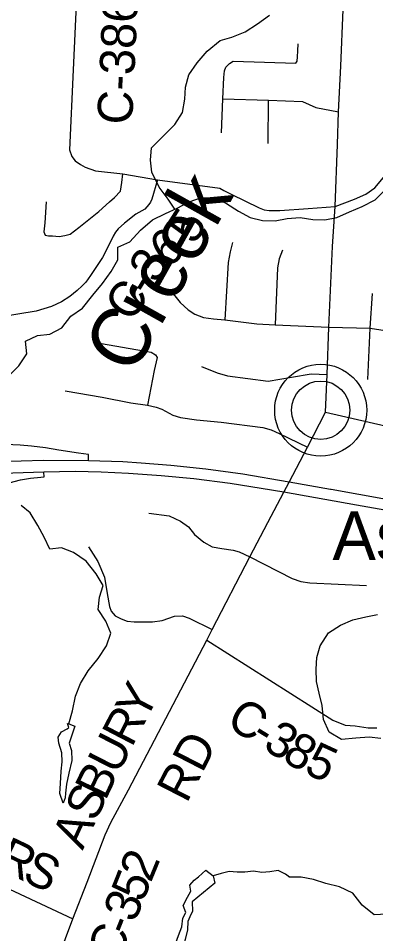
# Model space of a CAD drawing. Extents: x 0 to 34, y 0 to 22.
# Drawn here: x 4.659 to 4.948, y 14.941 to 15.682 of the extents above; entities that cross this region are included whole.
import ezdxf

# ---------------------------------------------------------------- set-up
doc = ezdxf.new("R2010")
doc.units = 0
for name, color, linetype in [('GM_X_County_Road', 7, 'Continuous'), ('GM_X_County_Road_Text', 7, 'Continuous'), ('GM_X_Interchange_Ramps', 7, 'Continuous'), ('GM_X_Interstate_Route', 7, 'Continuous'), ('GM_X_Minor_River', 7, 'Continuous'), ('GM_X_Minor_River_Text', 7, 'Continuous'), ('GM_X_Township_Road', 7, 'Continuous'), ('GM_X_Unincorporated', 7, 'Continuous'), ('GM_X_Unincorporated_Location', 7, 'Continuous'), ('GM_X_Unincorporated_Text', 7, 'Continuous')]:
    doc.layers.add(name, color=color, linetype=linetype)

msp = doc.modelspace()

# ---------------------------------------------------------------- linework, layer by layer
at = {"layer": 'GM_X_County_Road'}
msp.add_line((4.70658, 15.70999), (4.70334, 15.63991), dxfattribs=at)
for points in [[(4.9073, 15.36317), (4.90862, 15.39378), (4.91013, 15.43191), (4.91317, 15.4971), (4.91508, 15.52949), (4.91706, 15.57965), (4.91782, 15.606), (4.91971, 15.64287), (4.9218, 15.68884), (4.92284, 15.70486), (4.92616, 15.78353)], [(4.70334, 15.63991), (4.70036, 15.57533), (4.70231, 15.56995), (4.705, 15.56653), (4.70916, 15.56359), (4.71307, 15.56139), (4.72134, 15.55847), (4.74348, 15.55606), (4.77156, 15.55104)], [(4.77156, 15.55104), (4.82203, 15.54434), (4.82522, 15.54256), (4.83122, 15.53957), (4.8537, 15.52844), (4.8578, 15.52693), (4.86196, 15.52625), (4.87037, 15.52625), (4.89351, 15.52777), (4.91508, 15.52949), (4.9309, 15.53552), (4.93992, 15.53948), (4.94729, 15.54461), (4.95571, 15.55461), (4.97796, 15.58453), (4.98766, 15.58316)], [(4.77156, 15.55104), (4.76692, 15.53545), (4.76598, 15.53298), (4.76455, 15.53114), (4.76143, 15.52741), (4.75393, 15.52322), (4.74487, 15.51614), (4.73961, 15.51137), (4.73766, 15.5088), (4.7357, 15.5055), (4.73264, 15.49926), (4.72714, 15.48826), (4.71736, 15.47358), (4.71369, 15.46845), (4.71148, 15.46615)], [(4.71148, 15.46615), (4.71075, 15.46539), (4.70672, 15.46148), (4.70073, 15.45671), (4.694, 15.4523), (4.68593, 15.44864), (4.67345, 15.44497), (4.64191, 15.43982)], [(4.86082, 15.27396), (4.87359, 15.29836), (4.8779, 15.30659), (4.89275, 15.33488), (4.9073, 15.36317)], [(4.9073, 15.36317), (4.9557, 15.35212), (4.99857, 15.34333), (5.06724, 15.33122), (5.08926, 15.32733), (5.21435, 15.30577), (5.22323, 15.30424), (5.33237, 15.28586), (5.36275, 15.28074)], [(4.69129, 14.92158), (4.70295, 14.95352), (4.7147, 14.983), (4.72914, 15.02146), (4.73385, 15.03124), (4.74797, 15.05769), (4.81147, 15.17891), (4.81564, 15.1874), (4.8463, 15.24622), (4.86082, 15.27396)], [(4.31741, 15.19756), (4.3442, 15.17748), (4.34773, 15.17417), (4.35138, 15.1682), (4.35443, 15.16053), (4.37218, 15.09005), (4.37522, 15.08099), (4.3785, 15.0784), (4.38451, 15.07627), (4.3984, 15.07474), (4.42425, 15.07063), (4.44456, 15.06505), (4.46552, 15.0586), (4.52756, 15.03587), (4.55688, 15.0232), (4.58247, 15.0098), (4.70295, 14.95352)], [(4.81147, 15.17891), (4.91321, 15.11411), (4.92317, 15.11007), (4.9315, 15.1095), (4.9419, 15.10792), (4.94892, 15.10794)]]:
    msp.add_lwpolyline(points, dxfattribs=at)
at = {"layer": 'GM_X_Interchange_Ramps'}
for points in [[(4.71588, 15.32379), (4.71581, 15.32902), (4.70754, 15.33007), (4.6918, 15.33238), (4.68088, 15.33427), (4.66975, 15.33574), (4.66052, 15.33658), (4.64876, 15.337), (4.63491, 15.33721), (4.61035, 15.33658), (4.60816, 15.33671)], [(4.54337, 15.27986), (4.54738, 15.27883), (4.55536, 15.27736), (4.56081, 15.27631), (4.5669, 15.27569), (4.57299, 15.27547), (4.57971, 15.27611), (4.58621, 15.27716), (4.59356, 15.27946), (4.60217, 15.28324), (4.63113, 15.29752), (4.63722, 15.30067), (4.64415, 15.3034), (4.6517, 15.30613), (4.66073, 15.30844), (4.66891, 15.30991), (4.6771, 15.31075), (4.6798, 15.31082), (4.67967, 15.31478)]]:
    msp.add_lwpolyline(points, dxfattribs=at)
at = {"layer": 'GM_X_Interstate_Route'}
for points in [[(5.64651, 15.36912), (5.6198, 15.3541), (5.48013, 15.27959), (5.45117, 15.26555), (5.42683, 15.25634), (5.40347, 15.24943), (5.37737, 15.24329), (5.35697, 15.24022), (5.32769, 15.23748), (5.30422, 15.23693), (5.28196, 15.23792), (5.25893, 15.24022), (5.23393, 15.24406), (4.95659, 15.29264), (4.9119, 15.30056)], [(5.6228, 15.34646), (5.47854, 15.26884), (5.45002, 15.25579), (5.42392, 15.24614), (5.4032, 15.24011), (5.37896, 15.23452), (5.35518, 15.23103), (5.33257, 15.2286), (5.31108, 15.22805), (5.28706, 15.2286), (5.26206, 15.2309), (5.23563, 15.23485), (5.01027, 15.27433), (4.93252, 15.28792), (4.87359, 15.29836), (4.85542, 15.30141), (4.8302, 15.30547), (4.80103, 15.30931), (4.77438, 15.31183), (4.74806, 15.31359), (4.72602, 15.31479), (4.70507, 15.31523), (4.67967, 15.31478), (4.64629, 15.31366)], [(4.9119, 15.30056), (4.91141, 15.30065), (4.8779, 15.30659), (4.84056, 15.31304), (4.81062, 15.31709), (4.78222, 15.32017), (4.75842, 15.32203), (4.7434, 15.32302), (4.71588, 15.32379), (4.67936, 15.32422), (4.64295, 15.32313), (4.61202, 15.32104), (4.59195, 15.31918), (4.56892, 15.31633), (4.56287, 15.31551)]]:
    msp.add_lwpolyline(points, dxfattribs=at)
at = {"layer": 'GM_X_Minor_River'}
for points in [[(4.78562, 15.52729), (4.78007, 15.53533), (4.77284, 15.54502), (4.76694, 15.55738), (4.7658, 15.56688), (4.76675, 15.57696), (4.77626, 15.58627), (4.78558, 15.59578), (4.79166, 15.60547), (4.79375, 15.61631), (4.79432, 15.626), (4.7968, 15.63589), (4.80364, 15.64558), (4.81163, 15.65509), (4.82209, 15.66364), (4.8316, 15.66649), (4.84244, 15.67068), (4.85252, 15.67733), (4.86222, 15.68437)], [(4.6498, 15.39106), (4.65931, 15.40075), (4.66596, 15.41026), (4.66482, 15.42071), (4.67452, 15.42527), (4.68441, 15.42622), (4.6943, 15.43136), (4.70152, 15.44086), (4.71103, 15.44732), (4.71921, 15.45777), (4.7272, 15.46728), (4.73404, 15.47697), (4.73937, 15.48648), (4.73937, 15.49655), (4.74926, 15.50092), (4.75782, 15.51043), (4.76752, 15.5186), (4.77798, 15.52392), (4.78749, 15.5281), (4.79719, 15.53324), (4.80707, 15.53685), (4.81773, 15.53647), (4.82724, 15.53191), (4.83694, 15.52563), (4.84645, 15.5205), (4.85634, 15.51822), (4.8668, 15.51784), (4.8765, 15.51974), (4.88696, 15.5205), (4.89704, 15.51898), (4.90674, 15.51879), (4.91644, 15.5207), (4.92671, 15.52507), (4.93717, 15.52944), (4.94763, 15.53495), (4.95714, 15.54465)], [(4.69984, 15.11124), (4.70289, 15.12169), (4.70517, 15.13348), (4.70935, 15.14375), (4.71544, 15.15401), (4.72361, 15.1639), (4.73027, 15.17416), (4.73388, 15.18443), (4.72989, 15.19413), (4.72361, 15.20363), (4.72456, 15.21352), (4.7276, 15.22302), (4.7219, 15.23253), (4.71391, 15.2426), (4.70364, 15.24964), (4.69394, 15.25344), (4.68443, 15.2523), (4.67986, 15.262), (4.67491, 15.2715), (4.66864, 15.28177), (4.66122, 15.28773)], [(4.95223, 15.09923), (4.94272, 15.10038), (4.93188, 15.09943), (4.92028, 15.09848), (4.91039, 15.10437), (4.90583, 15.11464), (4.90468, 15.12586), (4.90221, 15.13593), (4.90012, 15.14544), (4.89993, 15.15533), (4.90031, 15.16483), (4.90316, 15.17434), (4.90981, 15.18461), (4.91951, 15.19088), (4.92959, 15.19525), (4.94006, 15.19772), (4.94956, 15.19943)], [(4.69984, 15.11124), (4.70468, 15.10925), (4.70007, 15.09546), (4.70205, 15.08953), (4.70229, 15.08155), (4.69982, 15.07114), (4.69795, 15.06224), (4.69725, 15.05503), (4.69699, 15.05124), (4.69521, 15.04709), (4.69269, 15.05493), (4.69302, 15.0629), (4.69377, 15.07296), (4.69447, 15.08036), (4.69422, 15.08777), (4.69189, 15.09561), (4.69122, 15.10037), (4.69396, 15.10469), (4.69837, 15.10708), (4.69972, 15.1082), (4.69889, 15.11137)], [(4.69892, 15.11128), (4.69984, 15.11124)], [(4.81657, 14.98808), (4.81799, 14.98216), (4.79966, 14.96729), (4.79972, 14.95969), (4.79774, 14.95516), (4.79596, 14.95139), (4.79584, 14.94455), (4.7938, 14.9368), (4.79195, 14.92942), (4.78942, 14.92604), (4.78756, 14.92836), (4.78613, 14.93332), (4.78853, 14.93993), (4.79132, 14.94691), (4.79201, 14.95393), (4.79437, 14.95845), (4.79239, 14.96419), (4.79574, 14.97097), (4.79849, 14.97586), (4.79781, 14.98063), (4.80131, 14.98475), (4.80478, 14.98753), (4.81057, 14.99275)], [(4.81057, 14.99275), (4.81657, 14.98808)], [(4.8783, 14.98724), (4.87515, 14.9895), (4.86912, 14.99246), (4.86245, 14.99144), (4.85597, 14.99079), (4.84915, 14.99187), (4.84229, 14.99123), (4.83583, 14.99116), (4.82938, 14.99184), (4.82307, 14.99006), (4.81657, 14.98808)], [(5.00043, 14.96108), (4.98762, 14.96669), (4.97678, 14.96612), (4.9667, 14.96194), (4.957, 14.95719), (4.94673, 14.95662), (4.93703, 14.96442), (4.92942, 14.97431), (4.91877, 14.97944), (4.90774, 14.98191), (4.89766, 14.98534), (4.88776, 14.98724), (4.87777, 14.98724)]]:
    msp.add_lwpolyline(points, dxfattribs=at)
at = {"layer": 'GM_X_Township_Road'}
for p, q in [((4.82331, 15.58901), (4.8245, 15.61658)), ((4.86097, 15.58036), (4.86122, 15.61538))]:
    msp.add_line(p, q, dxfattribs=at)
for points in [[(4.8245, 15.61658), (4.82521, 15.63377), (4.82574, 15.6391), (4.82673, 15.6423), (4.8297, 15.64527), (4.83265, 15.64691), (4.88345, 15.64542), (4.88436, 15.6471), (4.88467, 15.65067), (4.88497, 15.65547), (4.8852, 15.66103)], [(4.8245, 15.61658), (4.86122, 15.61538), (4.88881, 15.61439), (4.89965, 15.60946), (4.91782, 15.606)], [(4.68152, 15.53338), (4.68055, 15.51627), (4.67969, 15.50905), (4.68079, 15.50636), (4.68336, 15.50587), (4.68666, 15.50587), (4.69216, 15.50526), (4.69669, 15.50599), (4.70097, 15.50721), (4.70782, 15.5126), (4.72408, 15.52556), (4.73264, 15.53338), (4.7368, 15.53681), (4.74169, 15.54195), (4.74267, 15.54879), (4.74348, 15.55606)], [(4.83218, 15.50038), (4.83033, 15.4928), (4.82868, 15.48427), (4.82601, 15.43773)], [(4.87267, 15.49433), (4.86987, 15.4872), (4.8686, 15.47994), (4.86656, 15.43379)], [(4.78347, 15.45983), (4.78997, 15.45193), (4.79647, 15.44594), (4.80169, 15.44251), (4.80869, 15.43983), (4.81694, 15.43873), (4.82601, 15.43773), (4.85185, 15.43449), (4.86656, 15.43379), (4.91013, 15.43191)], [(4.94162, 15.38954), (4.94353, 15.43121), (4.94528, 15.45925)], [(4.91013, 15.43191), (4.94353, 15.43121), (4.97796, 15.42564), (5.04969, 15.41174), (5.05789, 15.41342), (5.06818, 15.41785), (5.0756, 15.41857), (5.09845, 15.41534), (5.19458, 15.39992), (5.29182, 15.38476), (5.32061, 15.38035)], [(4.72005, 15.41977), (4.76652, 15.41158), (4.76994, 15.40962), (4.77117, 15.4073), (4.76872, 15.39678), (4.76351, 15.36879)], [(4.80703, 15.40008), (4.81984, 15.39491), (4.82821, 15.39269), (4.86097, 15.38826), (4.87994, 15.39146), (4.89591, 15.39425), (4.90862, 15.39378)], [(4.69683, 15.38044), (4.72688, 15.37536), (4.74992, 15.37083), (4.76351, 15.36879), (4.77043, 15.36731), (4.77508, 15.3656), (4.78389, 15.36083), (4.79012, 15.35875), (4.80309, 15.35704), (4.82297, 15.35506), (4.85683, 15.35066), (4.86343, 15.34899), (4.86981, 15.3458), (4.89275, 15.33488)], [(4.76442, 15.28141), (4.78103, 15.27927), (4.79024, 15.27516), (4.79648, 15.27055), (4.80158, 15.26414), (4.809, 15.25797), (4.81588, 15.25428), (4.82361, 15.2528), (4.83265, 15.25148), (4.83758, 15.25017), (4.8463, 15.24622)], [(4.71586, 15.2542), (4.72317, 15.24248), (4.72865, 15.22969), (4.73078, 15.21659), (4.73283, 15.20608), (4.73413, 15.20235), (4.73721, 15.19858), (4.7422, 15.19596), (4.747, 15.19421), (4.75271, 15.19375), (4.76748, 15.19367), (4.77532, 15.19474), (4.78537, 15.19824), (4.79184, 15.19855), (4.79725, 15.19657), (4.81564, 15.1874)], [(4.8463, 15.24622), (4.8805, 15.22879), (4.88756, 15.22617), (4.8948, 15.22518), (4.94043, 15.22301)]]:
    msp.add_lwpolyline(points, dxfattribs=at)
at = {"layer": 'GM_X_Unincorporated'}
for radius in [0.0372, 0.02358]:
    msp.add_circle((4.9035, 15.36479), radius, dxfattribs=at)
at = {"layer": 'GM_X_Unincorporated_Location'}
msp.add_line((4.9035, 15.36479), (4.9035, 15.36479), dxfattribs=at)

# ---------------------------------------------------------------- texts
at = {"layer": 'GM_X_County_Road_Text'}
for s, height, rotation, p in [('C-386', 0.028409, 87.35268, (4.75102, 15.59537)), ('5', 0.02841, 57.34224, (4.80127, 15.49782)), ('6', 0.02841, 33.65687, (4.77778, 15.47904)), ('3', 0.02841, 59.99311, (4.77137, 15.46638)), ('C', 0.02841, 54.1699, (4.74994, 15.43485)), ('-', 0.02841, 58.70813, (4.76496, 15.45581)), ('Y', 0.02841, 62.51376, (4.76152, 15.11206)), ('R', 0.02841, 62.51503, (4.75075, 15.09136)), ('C', 0.02841, 328.41909, (4.82585, 15.10983)), ('3', 0.02841, 328.69515, (4.8558, 15.09143)), ('U', 0.02841, 62.88023, (4.73938, 15.06915)), ('RD', 0.028409, 62.77168, (4.79513, 15.0462)), ('-', 0.02841, 328.48168, (4.84576, 15.09759)), ('8', 0.02841, 329.50712, (4.87113, 15.08211)), ('5', 0.02841, 335.25861, (4.88897, 15.07179)), ('B', 0.02841, 64.28151, (4.72933, 15.04829)), ('S', 0.02841, 65.28392, (4.72137, 15.031)), ('A', 0.02841, 65.39023, (4.71097, 15.00829)), ('R', 0.02841, 334.59827, (4.64005, 14.99486)), ('S', 0.02841, 334.59947, (4.66112, 14.98485)), ('2', 0.02841, 67.64533, (4.76609, 14.98203)), ('5', 0.02841, 68.24641, (4.75963, 14.96585)), ('3', 0.02841, 68.33629, (4.75318, 14.9496)), ('C', 0.02841, 68.36673, (4.74027, 14.91707)), ('-', 0.02841, 68.3631, (4.74888, 14.93876))]:
    msp.add_text(s, height=height, rotation=rotation, dxfattribs=at).set_placement(p)
at = {"layer": 'GM_X_Minor_River_Text'}
msp.add_text('Creek', height=0.047321, rotation=60.73902, dxfattribs=at).set_placement((4.75129, 15.39156))
at = {"layer": 'GM_X_Unincorporated_Text'}
msp.add_text('Asbury', height=0.039489, rotation=0.00001, dxfattribs=at).set_placement((4.91296, 15.24352))

doc.saveas('drawing.dxf')
